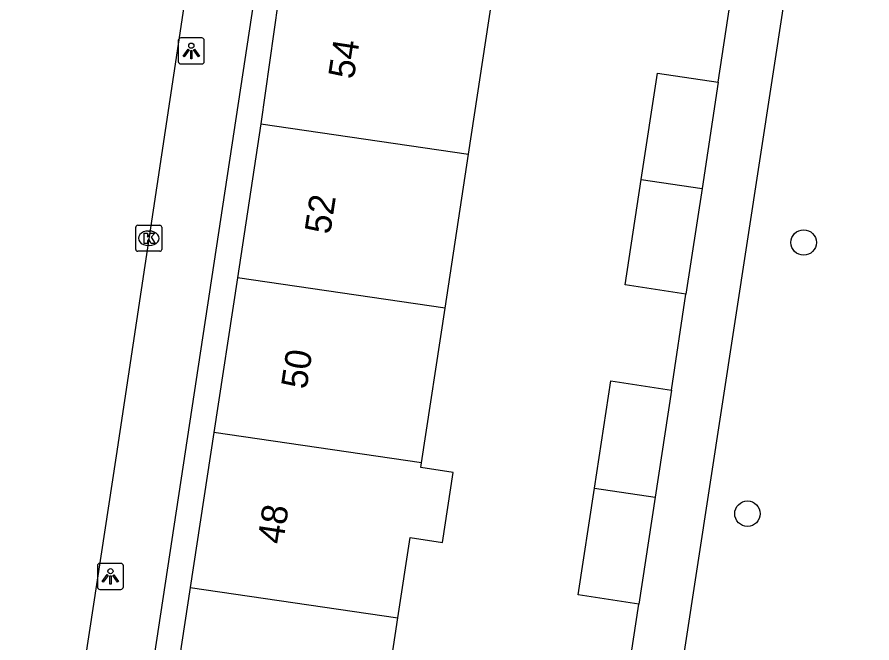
# Model space of a CAD drawing. Extents: x 161084 to 161928, y 385355 to 386522.
# Drawn here: x 161749.15 to 161782.03, y 385581.01 to 385605.07 of the extents above; entities that cross this region are included whole.
import ezdxf

# ---------------------------------------------------------------- set-up
doc = ezdxf.new("R2010")
doc.units = 0
for name, color, linetype in [('IMGEO_Boom', 7, 'Continuous'), ('IMGEO_Kolk', 7, 'Continuous'), ('IMGEO_Lichtpunt', 7, 'Continuous'), ('IMGEO_Pand', 7, 'Continuous'), ('IMGEO_Pand_nummerreeks', 7, 'Continuous'), ('IMGEO_Rijbaan_lokaal_open', 7, 'Continuous'), ('IMGEO_Voetpad_open', 7, 'Continuous')]:
    doc.layers.add(name, color=color, linetype=linetype)

msp = doc.modelspace()

# ---------------------------------------------------------------- linework, layer by layer
at = {"layer": 'IMGEO_Boom'}
for centre in [(161779.407, 385596.404), (161777.246, 385585.98)]:
    msp.add_circle(centre, 0.489, dxfattribs=at)
at = {"layer": 'IMGEO_Kolk'}
for p, q in [((161753.719, 385596.139), (161753.719, 385596.991)), ((161753.794, 385597.065), (161754.646, 385597.065)), ((161754.72, 385596.991), (161754.72, 385596.139)), ((161754.207, 385596.845), (161754.232, 385596.845)), ((161754.646, 385596.065), (161753.794, 385596.065)), ((161754.23, 385596.285), (161754.205, 385596.285))]:
    msp.add_line(p, q, dxfattribs=at)
for points in [[(161753.719, 385596.139), (161753.719, 385596.991)], [(161753.794, 385597.065), (161754.646, 385597.065)], [(161754.72, 385596.991), (161754.72, 385596.139)], [(161754.04, 385596.765), (161754.163, 385596.765), (161754.163, 385596.614), (161754.293, 385596.765), (161754.457, 385596.765), (161754.311, 385596.614), (161754.464, 385596.365), (161754.312, 385596.365), (161754.227, 385596.529), (161754.163, 385596.462), (161754.163, 385596.365), (161754.04, 385596.365), (161754.04, 385596.765)], [(161754.646, 385596.065), (161753.794, 385596.065)]]:
    msp.add_lwpolyline(points, dxfattribs=at)
for centre, start, end in [((161753.796, 385596.989), 91.552, 178.448), ((161753.796, 385596.989), 91.552, 178.448), ((161754.644, 385596.989), 1.552, 88.448), ((161754.644, 385596.989), 1.552, 88.448), ((161753.796, 385596.141), 181.552, 268.448), ((161753.796, 385596.141), 181.552, 268.448), ((161754.644, 385596.141), 271.552, 358.448), ((161754.644, 385596.141), 271.552, 358.448)]:
    msp.add_arc(centre, 0.0765, start, end, dxfattribs=at)
for centre, major_axis, ratio, start_param, end_param in [((161754.206, 385596.565), (-0.387, 0.002), 0.722429, 4.712389, 7.853982), ((161754.231, 385596.565), (-0.39, 0.002), 0.717154, 1.570796, 4.712389)]:
    msp.add_ellipse(centre, major_axis=major_axis, ratio=ratio, start_param=start_param, end_param=end_param, dxfattribs=at)
at = {"layer": 'IMGEO_Lichtpunt'}
for p, q in [((161756.257, 385604.264), (161755.449, 385604.264)), ((161756.257, 385604.264), (161755.449, 385604.264)), ((161755.355, 385604.169), (161755.355, 385603.362)), ((161755.355, 385604.169), (161755.355, 385603.362)), ((161756.351, 385603.362), (161756.351, 385604.169)), ((161756.351, 385603.362), (161756.351, 385604.169)), ((161755.449, 385603.268), (161756.257, 385603.268)), ((161755.449, 385603.268), (161756.257, 385603.268)), ((161752.245, 385583.972), (161752.245, 385583.165)), ((161752.245, 385583.972), (161752.245, 385583.165)), ((161753.147, 385584.067), (161752.339, 385584.067)), ((161753.147, 385584.067), (161752.339, 385584.067)), ((161753.241, 385583.165), (161753.241, 385583.972)), ((161753.241, 385583.165), (161753.241, 385583.972)), ((161752.339, 385583.071), (161753.147, 385583.071)), ((161752.339, 385583.071), (161753.147, 385583.071))]:
    msp.add_line(p, q, dxfattribs=at)
for points in [[(161755.729, 385603.833), (161755.768, 385603.805), (161755.58, 385603.543), (161755.542, 385603.57), (161755.729, 385603.833)], [(161755.831, 385603.785), (161755.878, 385603.785), (161755.878, 385603.463), (161755.831, 385603.463), (161755.831, 385603.785)], [(161755.941, 385603.805), (161755.979, 385603.832), (161756.166, 385603.57), (161756.127, 385603.542), (161755.941, 385603.805)], [(161752.619, 385583.636), (161752.658, 385583.608), (161752.47, 385583.346), (161752.432, 385583.373), (161752.619, 385583.636)], [(161752.721, 385583.588), (161752.768, 385583.588), (161752.768, 385583.266), (161752.721, 385583.266), (161752.721, 385583.588)], [(161752.831, 385583.608), (161752.869, 385583.635), (161753.056, 385583.373), (161753.017, 385583.345), (161752.831, 385583.608)]]:
    msp.add_lwpolyline(points, dxfattribs=at)
for centre in [(161755.854, 385603.967), (161752.744, 385583.77)]:
    msp.add_circle(centre, 0.0994, dxfattribs=at)
for centre, start, end in [((161755.449, 385604.169), 90, 180), ((161755.449, 385604.169), 90, 180), ((161756.257, 385604.169), 0, 90), ((161756.257, 385604.169), 0, 90), ((161755.449, 385603.362), 180, 270), ((161755.449, 385603.362), 180, 270), ((161756.257, 385603.362), 270, 0), ((161756.257, 385603.362), 270, 360), ((161752.339, 385583.972), 90, 180), ((161752.339, 385583.972), 90, 180), ((161753.147, 385583.972), 0, 90), ((161753.147, 385583.972), 0, 90), ((161752.339, 385583.165), 180, 270), ((161752.339, 385583.165), 180, 270), ((161753.147, 385583.165), 270, 0), ((161753.147, 385583.165), 270, 360)]:
    msp.add_arc(centre, 0.0946, start, end, dxfattribs=at)
at = {"layer": 'IMGEO_Pand'}
for points in [[(161759.367, 385606.876), (161758.527, 385600.961)], [(161766.515, 385599.795), (161767.411, 385605.677)], [(161773.164, 385598.824), (161773.786, 385602.917), (161776.119, 385602.562)], [(161776.119, 385602.562), (161775.499, 385598.484)], [(161758.527, 385600.961), (161757.625, 385595.04)], [(161758.527, 385600.961), (161766.515, 385599.795)], [(161765.613, 385593.874), (161766.515, 385599.795)], [(161774.881, 385594.416), (161772.548, 385594.771), (161773.164, 385598.824)], [(161773.164, 385598.824), (161775.499, 385598.484)], [(161775.499, 385598.484), (161774.881, 385594.416)], [(161757.625, 385595.04), (161756.72, 385589.098)], [(161765.613, 385593.874), (161757.625, 385595.04)], [(161764.708, 385587.932), (161765.613, 385593.874)], [(161771.361, 385586.961), (161771.987, 385591.083), (161774.32, 385590.728)], [(161774.32, 385590.728), (161773.696, 385586.62)], [(161756.72, 385589.098), (161755.814, 385583.147)], [(161764.708, 385587.932), (161756.72, 385589.098)], [(161763.801, 385581.981), (161764.271, 385585.066), (161765.516, 385584.876), (161765.926, 385587.564), (161764.681, 385587.754), (161764.708, 385587.932)], [(161773.07, 385582.502), (161770.737, 385582.857), (161771.361, 385586.961)], [(161771.361, 385586.961), (161773.696, 385586.62)], [(161773.696, 385586.62), (161773.07, 385582.502)], [(161755.814, 385583.147), (161754.905, 385577.176)], [(161755.814, 385583.147), (161763.801, 385581.981)], [(161762.883, 385575.96), (161763.801, 385581.981)]]:
    msp.add_lwpolyline(points, dxfattribs=at)
at = {"layer": 'IMGEO_Rijbaan_lokaal_open'}
msp.add_lwpolyline([(161759.266, 385629.984), (161758.804, 385627.019), (161755.485, 385604.964), (161752.959, 385588.197), (161746.133, 385543.607)], dxfattribs=at)
at = {"layer": 'IMGEO_Voetpad_open'}
for points in [[(161749.416, 385547.492), (161758.437, 385606.815), (161762.136, 385630.764)], [(161782.033, 385627.684), (161773.386, 385571.42)], [(161776.119, 385602.562), (161776.737, 385606.625)], [(161774.32, 385590.728), (161774.881, 385594.416)], [(161772.508, 385578.805), (161773.07, 385582.502)]]:
    msp.add_lwpolyline(points, dxfattribs=at)

# ---------------------------------------------------------------- texts
at = {"layer": 'IMGEO_Pand_nummerreeks'}
for s, rotation, p in [('54', 81.3409, (161762.102, 385602.652)), ('52', 81.3409, (161761.194, 385596.69)), ('50', 81.3409, (161760.288, 385590.736)), ('48', 81.3428, (161759.38, 385584.777))]:
    msp.add_text(s, height=1, rotation=rotation, dxfattribs=at).set_placement(p)

doc.saveas('drawing.dxf')
